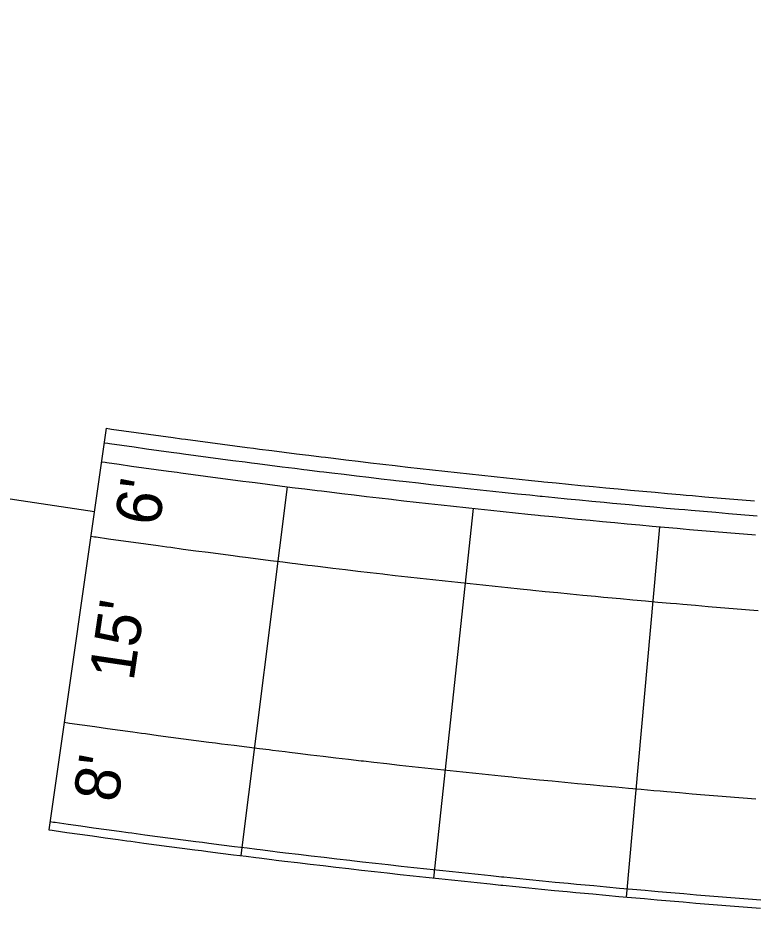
# Model space of a CAD drawing. Extents: x 2145147 to 2158018, y 137519 to 148068.
# Drawn here: x 2150959.2 to 2151017.9, y 142319.2 to 142390.2 of the extents above; entities that cross this region are included whole.
import ezdxf

# ---------------------------------------------------------------- set-up
doc = ezdxf.new("R2010")
doc.units = 0
for name, color, linetype in [('PR_Align_Ramp_B', 7, 'Continuous'), ('PR_Curb_Back', 7, 'Continuous'), ('PR_Curb_Face', 7, 'Continuous'), ('PR_Dimensions', 7, 'Continuous'), ('PR_Joint_Contraction', 7, 'Continuous'), ('PR_Joint_Long', 7, 'Continuous'), ('PR_Parapet', 7, 'Continuous'), ('PR_Retaining_Wall', 7, 'Continuous'), ('PR_Road_Concrete', 7, 'Continuous')]:
    doc.layers.add(name, color=color, linetype=linetype)

msp = doc.modelspace()

# ---------------------------------------------------------------- linework, layer by layer
at = {"layer": 'PR_Align_Ramp_B'}
msp.add_arc((2151085.747, 143191.052), 848.826, 152.505099, 261.840906, dxfattribs=at)
at = {"layer": 'PR_Curb_Back'}
msp.add_lwpolyline([(2150961.637, 142325.411), (2150961.925, 142325.37), (2150962.065, 142325.35), (2150963.085, 142325.205), (2150964.105, 142325.061), (2150965.125, 142324.918), (2150966.146, 142324.777), (2150967.166, 142324.636), (2150967.871, 142324.54), (2150968.187, 142324.497), (2150969.208, 142324.359), (2150970.229, 142324.223), (2150971.251, 142324.087), (2150972.272, 142323.953), (2150973.294, 142323.82), (2150973.823, 142323.751), (2150974.315, 142323.688), (2150975.337, 142323.557), (2150976.359, 142323.428), (2150977.382, 142323.3), (2150978.138, 142323.205), (2150978.404, 142323.172), (2150979.427, 142323.047), (2150979.78, 142323.003), (2150980.449, 142322.922), (2150981.472, 142322.799), (2150982.495, 142322.676), (2150983.518, 142322.555), (2150984.541, 142322.435), (2150985.565, 142322.317), (2150985.742, 142322.296), (2150986.588, 142322.199), (2150987.612, 142322.083), (2150988.636, 142321.968), (2150989.66, 142321.854), (2150990.684, 142321.742), (2150991.708, 142321.63), (2150991.709, 142321.63), (2150992.732, 142321.52), (2150993.757, 142321.411), (2150994.781, 142321.303), (2150995.806, 142321.197), (2150996.831, 142321.092), (2150997.68, 142321.005), (2150997.856, 142320.987), (2150998.881, 142320.884), (2150999.906, 142320.783), (2151000.931, 142320.682), (2151001.957, 142320.583), (2151002.982, 142320.485), (2151003.655, 142320.421), (2151004.008, 142320.388), (2151005.034, 142320.292), (2151006.06, 142320.198), (2151007.086, 142320.104), (2151008.112, 142320.012), (2151009.138, 142319.921), (2151009.635, 142319.878), (2151010.164, 142319.832), (2151011.191, 142319.743), (2151012.217, 142319.656), (2151013.244, 142319.57), (2151014.271, 142319.485), (2151015.298, 142319.402), (2151015.617, 142319.376), (2151016.325, 142319.319), (2151017.352, 142319.238), (2151018.379, 142319.158)], dxfattribs=at)
at = {"layer": 'PR_Curb_Face'}
msp.add_lwpolyline([(2150961.731, 142326.071), (2150962.02, 142326.03), (2150962.159, 142326.01), (2150963.178, 142325.865), (2150964.198, 142325.721), (2150965.217, 142325.578), (2150966.237, 142325.437), (2150967.257, 142325.297), (2150967.961, 142325.201), (2150968.277, 142325.158), (2150969.297, 142325.02), (2150970.317, 142324.884), (2150971.338, 142324.748), (2150972.359, 142324.614), (2150973.379, 142324.481), (2150973.908, 142324.413), (2150974.4, 142324.349), (2150975.422, 142324.219), (2150976.443, 142324.089), (2150977.464, 142323.961), (2150978.22, 142323.867), (2150978.486, 142323.834), (2150979.508, 142323.708), (2150979.861, 142323.665), (2150980.529, 142323.584), (2150981.552, 142323.46), (2150982.574, 142323.338), (2150983.596, 142323.217), (2150984.618, 142323.098), (2150985.641, 142322.979), (2150985.818, 142322.959), (2150986.664, 142322.862), (2150987.687, 142322.746), (2150988.71, 142322.631), (2150989.733, 142322.517), (2150990.756, 142322.404), (2150991.78, 142322.293), (2150991.781, 142322.293), (2150992.803, 142322.183), (2150993.827, 142322.074), (2150994.851, 142321.966), (2150995.875, 142321.86), (2150996.899, 142321.755), (2150997.747, 142321.668), (2150997.923, 142321.651), (2150998.947, 142321.548), (2150999.972, 142321.446), (2151000.996, 142321.346), (2151002.021, 142321.246), (2151003.045, 142321.148), (2151003.718, 142321.085), (2151004.07, 142321.052), (2151005.095, 142320.956), (2151006.12, 142320.862), (2151007.146, 142320.768), (2151008.171, 142320.676), (2151009.196, 142320.586), (2151009.693, 142320.542), (2151010.222, 142320.496), (2151011.248, 142320.408), (2151012.273, 142320.32), (2151013.299, 142320.235), (2151014.325, 142320.15), (2151015.351, 142320.066), (2151015.671, 142320.04), (2151016.377, 142319.984), (2151017.404, 142319.903), (2151018.43, 142319.823)], dxfattribs=at)
at = {"layer": 'PR_Joint_Contraction'}
for p, q in [((2150980.642, 142352.786), (2150976.959, 142323.349)), ((2150995.471, 142351.06), (2150992.309, 142321.562)), ((2151010.328, 142349.596), (2151007.688, 142320.047))]:
    msp.add_line(p, q, dxfattribs=at)
at = {"layer": 'PR_Joint_Long'}
for points in [[(2150964.995, 142348.838), (2150965.276, 142348.798), (2150965.413, 142348.779), (2150966.404, 142348.637), (2150967.397, 142348.497), (2150968.39, 142348.359), (2150969.383, 142348.221), (2150970.375, 142348.084), (2150971.061, 142347.991), (2150971.369, 142347.949), (2150972.362, 142347.815), (2150973.356, 142347.682), (2150974.349, 142347.55), (2150975.343, 142347.419), (2150976.337, 142347.29), (2150976.852, 142347.223), (2150977.331, 142347.162), (2150978.325, 142347.035), (2150979.32, 142346.909), (2150980.314, 142346.784), (2150981.05, 142346.692), (2150981.309, 142346.66), (2150982.304, 142346.538), (2150982.648, 142346.496), (2150983.299, 142346.416), (2150984.294, 142346.296), (2150985.289, 142346.177), (2150986.285, 142346.06), (2150987.28, 142345.943), (2150988.275, 142345.828), (2150988.449, 142345.808), (2150989.272, 142345.713), (2150990.268, 142345.6), (2150991.264, 142345.488), (2150992.26, 142345.378), (2150993.256, 142345.268), (2150994.253, 142345.16), (2150995.25, 142345.053), (2150996.246, 142344.947), (2150997.243, 142344.842), (2150998.24, 142344.738), (2150999.237, 142344.636), (2151000.063, 142344.552), (2151000.235, 142344.534), (2151001.232, 142344.434), (2151002.229, 142344.335), (2151003.227, 142344.237), (2151004.224, 142344.141), (2151005.222, 142344.045), (2151005.877, 142343.983), (2151006.221, 142343.951), (2151007.218, 142343.858), (2151008.216, 142343.766), (2151009.215, 142343.675), (2151010.213, 142343.586), (2151011.211, 142343.497), (2151011.694, 142343.455), (2151012.21, 142343.41), (2151013.209, 142343.324), (2151014.207, 142343.239), (2151015.206, 142343.155), (2151016.205, 142343.073), (2151017.204, 142342.991), (2151017.516, 142342.966), (2151018.204, 142342.911)], [(2150962.867, 142333.99), (2150963.152, 142333.949), (2150963.291, 142333.929), (2150964.301, 142333.786), (2150965.311, 142333.643), (2150966.321, 142333.502), (2150967.331, 142333.362), (2150968.341, 142333.223), (2150969.039, 142333.128), (2150969.353, 142333.085), (2150970.363, 142332.949), (2150971.374, 142332.813), (2150972.385, 142332.679), (2150973.397, 142332.546), (2150974.408, 142332.415), (2150974.932, 142332.347), (2150975.42, 142332.284), (2150976.432, 142332.155), (2150977.444, 142332.026), (2150978.455, 142331.899), (2150979.204, 142331.806), (2150979.468, 142331.774), (2150980.48, 142331.649), (2150980.831, 142331.606), (2150981.493, 142331.526), (2150982.505, 142331.403), (2150983.518, 142331.282), (2150984.531, 142331.162), (2150985.544, 142331.044), (2150986.557, 142330.926), (2150986.734, 142330.906), (2150987.571, 142330.81), (2150988.584, 142330.695), (2150989.598, 142330.581), (2150990.612, 142330.469), (2150991.626, 142330.357), (2150992.64, 142330.247), (2150993.654, 142330.138), (2150994.668, 142330.03), (2150995.683, 142329.923), (2150996.697, 142329.818), (2150997.712, 142329.713), (2150998.553, 142329.628), (2150998.727, 142329.61), (2150999.742, 142329.508), (2151000.757, 142329.408), (2151001.772, 142329.308), (2151002.787, 142329.21), (2151003.802, 142329.113), (2151004.469, 142329.049), (2151004.819, 142329.017), (2151005.834, 142328.922), (2151006.849, 142328.828), (2151007.865, 142328.736), (2151008.881, 142328.645), (2151009.897, 142328.555), (2151010.389, 142328.512), (2151010.914, 142328.466), (2151011.93, 142328.378), (2151012.946, 142328.292), (2151013.963, 142328.207), (2151014.979, 142328.123), (2151015.995, 142328.04), (2151016.313, 142328.015), (2151017.013, 142327.959), (2151018.029, 142327.878)]]:
    msp.add_lwpolyline(points, dxfattribs=at)
at = {"layer": 'PR_Parapet'}
msp.add_lwpolyline([(2150965.846, 142354.774), (2150966.125, 142354.734), (2150966.26, 142354.715), (2150967.246, 142354.575), (2150968.231, 142354.436), (2150969.217, 142354.298), (2150970.203, 142354.161), (2150971.189, 142354.026), (2150971.87, 142353.933), (2150972.175, 142353.891), (2150973.161, 142353.758), (2150974.148, 142353.626), (2150975.134, 142353.495), (2150976.121, 142353.365), (2150977.108, 142353.237), (2150977.62, 142353.171), (2150978.095, 142353.109), (2150979.082, 142352.983), (2150980.07, 142352.858), (2150981.057, 142352.734), (2150981.788, 142352.643), (2150982.045, 142352.612), (2150983.033, 142352.49), (2150983.375, 142352.448), (2150984.021, 142352.369), (2150985.009, 142352.25), (2150985.997, 142352.132), (2150986.986, 142352.015), (2150987.974, 142351.899), (2150988.963, 142351.785), (2150989.134, 142351.765), (2150989.952, 142351.671), (2150990.941, 142351.559), (2150991.93, 142351.448), (2150992.919, 142351.338), (2150993.908, 142351.229), (2150994.898, 142351.122), (2150994.899, 142351.122), (2150995.887, 142351.015), (2150996.877, 142350.91), (2150997.867, 142350.806), (2150998.857, 142350.703), (2150999.847, 142350.601), (2151000.667, 142350.518), (2151000.837, 142350.5), (2151001.827, 142350.401), (2151002.818, 142350.303), (2151003.808, 142350.206), (2151004.799, 142350.11), (2151005.79, 142350.015), (2151006.44, 142349.953), (2151006.781, 142349.921), (2151007.772, 142349.829), (2151008.763, 142349.738), (2151009.754, 142349.647), (2151010.745, 142349.559), (2151011.737, 142349.471), (2151012.216, 142349.429), (2151012.728, 142349.384), (2151013.72, 142349.299), (2151014.712, 142349.214), (2151015.703, 142349.131), (2151016.695, 142349.049), (2151017.687, 142348.969), (2151017.996, 142348.944)], dxfattribs=at)
at = {"layer": 'PR_Retaining_Wall'}
for points in [[(2150966.23, 142357.448), (2150966.508, 142357.408), (2150966.642, 142357.388), (2150967.624, 142357.249), (2150968.607, 142357.11), (2150969.589, 142356.973), (2150970.572, 142356.836), (2150971.555, 142356.701), (2150972.234, 142356.609), (2150972.538, 142356.567), (2150973.521, 142356.435), (2150974.504, 142356.303), (2150975.488, 142356.172), (2150976.472, 142356.043), (2150977.455, 142355.915), (2150977.965, 142355.849), (2150978.439, 142355.788), (2150979.423, 142355.662), (2150980.408, 142355.537), (2150981.392, 142355.414), (2150982.121, 142355.323), (2150982.377, 142355.292), (2150983.361, 142355.17), (2150983.702, 142355.129), (2150984.346, 142355.05), (2150985.331, 142354.931), (2150986.316, 142354.814), (2150987.301, 142354.697), (2150988.287, 142354.582), (2150989.272, 142354.468), (2150989.443, 142354.448), (2150990.258, 142354.355), (2150991.244, 142354.243), (2150992.23, 142354.132), (2150993.216, 142354.022), (2150994.202, 142353.914), (2150995.188, 142353.807), (2150995.189, 142353.806), (2150996.175, 142353.7), (2150997.161, 142353.596), (2150998.148, 142353.492), (2150999.135, 142353.389), (2151000.121, 142353.288), (2151000.939, 142353.204), (2151001.109, 142353.187), (2151002.096, 142353.088), (2151003.083, 142352.99), (2151004.07, 142352.893), (2151005.058, 142352.798), (2151006.045, 142352.703), (2151006.694, 142352.642), (2151007.033, 142352.61), (2151008.021, 142352.518), (2151009.009, 142352.427), (2151009.997, 142352.337), (2151010.985, 142352.248), (2151011.973, 142352.161), (2151012.451, 142352.119), (2151012.962, 142352.075), (2151013.95, 142351.989), (2151014.939, 142351.905), (2151015.927, 142351.823), (2151016.916, 142351.741), (2151017.905, 142351.66)], [(2150966.064, 142356.293), (2150966.342, 142356.253), (2150966.477, 142356.233), (2150967.461, 142356.094), (2150968.445, 142355.955), (2150969.428, 142355.817), (2150970.412, 142355.681), (2150971.397, 142355.545), (2150972.077, 142355.453), (2150972.381, 142355.411), (2150973.366, 142355.278), (2150974.35, 142355.146), (2150975.335, 142355.016), (2150976.32, 142354.886), (2150977.305, 142354.758), (2150977.816, 142354.692), (2150978.291, 142354.631), (2150979.276, 142354.505), (2150980.262, 142354.38), (2150981.248, 142354.256), (2150981.977, 142354.165), (2150982.233, 142354.134), (2150983.219, 142354.012), (2150983.56, 142353.971), (2150984.206, 142353.892), (2150985.192, 142353.773), (2150986.178, 142353.655), (2150987.165, 142353.539), (2150988.152, 142353.423), (2150989.139, 142353.309), (2150989.31, 142353.289), (2150990.126, 142353.195), (2150991.113, 142353.083), (2150992.1, 142352.972), (2150993.087, 142352.863), (2150994.075, 142352.754), (2150995.063, 142352.647), (2150995.064, 142352.647), (2150996.05, 142352.54), (2150997.038, 142352.435), (2150998.026, 142352.331), (2150999.015, 142352.229), (2151000.003, 142352.127), (2151000.822, 142352.044), (2151000.991, 142352.027), (2151001.98, 142351.927), (2151002.968, 142351.829), (2151003.957, 142351.732), (2151004.946, 142351.636), (2151005.935, 142351.542), (2151006.584, 142351.48), (2151006.924, 142351.448), (2151007.913, 142351.356), (2151008.903, 142351.265), (2151009.892, 142351.175), (2151010.881, 142351.086), (2151011.871, 142350.999), (2151012.35, 142350.957), (2151012.861, 142350.912), (2151013.851, 142350.827), (2151014.841, 142350.743), (2151015.831, 142350.66), (2151016.821, 142350.578), (2151017.811, 142350.497), (2151018.119, 142350.473)]]:
    msp.add_lwpolyline(points, dxfattribs=at)
at = {"layer": 'PR_Road_Concrete'}
msp.add_line((2150966.23, 142357.448), (2150961.637, 142325.411), dxfattribs=at)

# ---------------------------------------------------------------- texts
at = {"layer": 'PR_Dimensions'}
for s, p in [("6'", (2150970.444, 142349.565)), ("15'", (2150968.396, 142337.209)), ("8'", (2150967.146, 142327.512))]:
    msp.add_text(s, height=3.6, rotation=81.56301, dxfattribs=at).set_placement(p)

doc.saveas('drawing.dxf')
